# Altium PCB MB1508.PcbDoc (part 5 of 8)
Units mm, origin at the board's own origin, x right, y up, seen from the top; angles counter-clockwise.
Board outline 129 x 77 mm, 4 copper layers (Top Layer, GND, POWER, Bottom Layer), stack 1.582 mm thick; 399 components, 297 nets, 1407 pads, 1316 vias.
Unrouted connection lines stored in the file: 535.
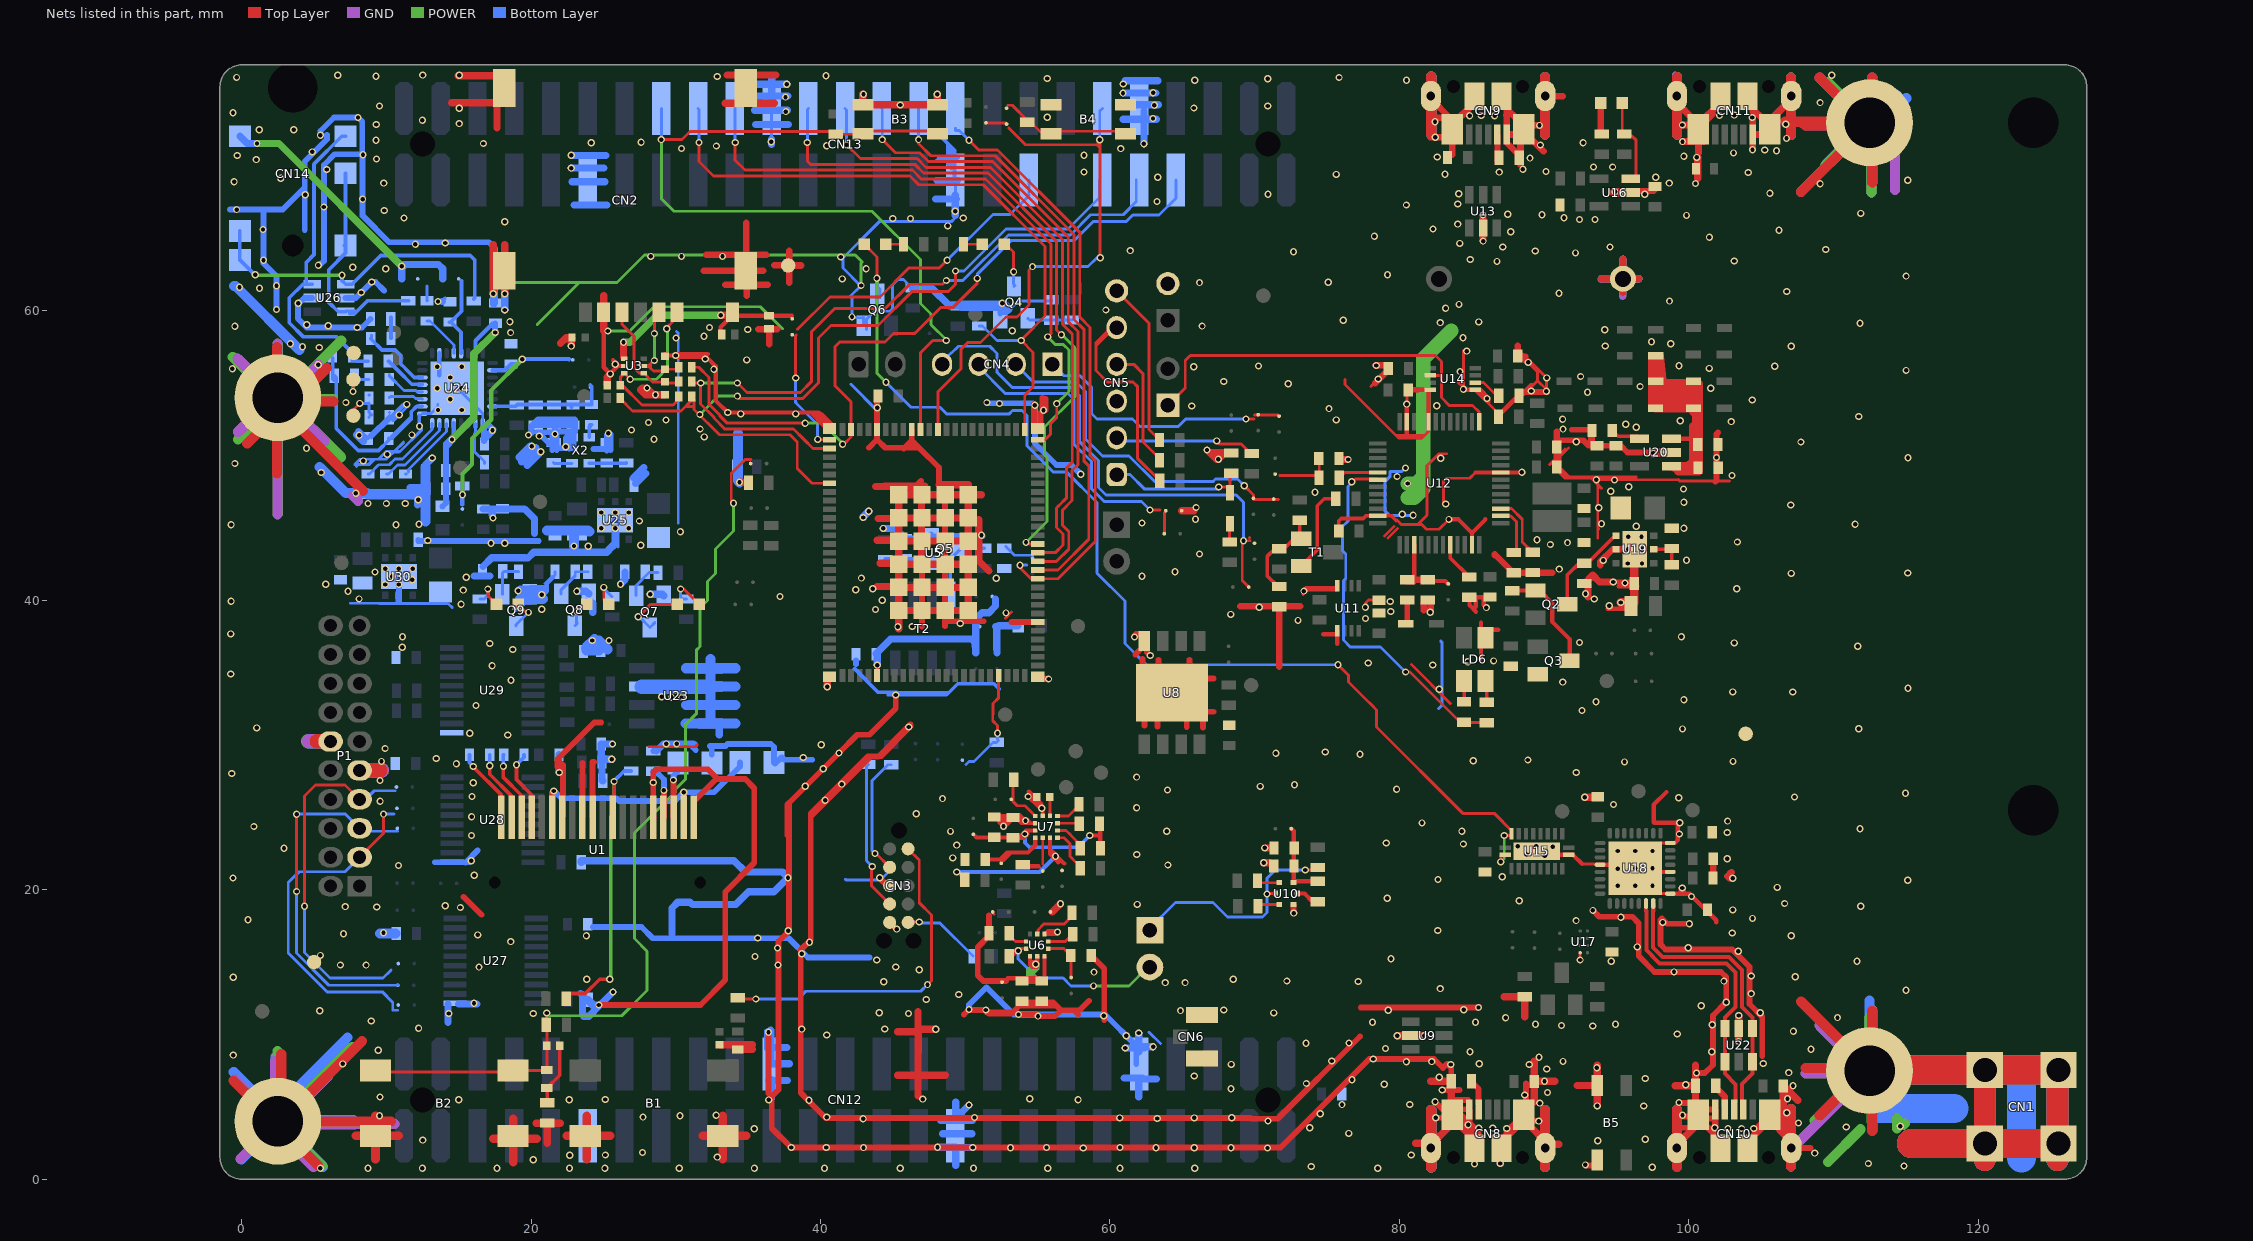
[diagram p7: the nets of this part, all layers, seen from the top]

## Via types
v1: diameter 0.5, hole 0.3, Top Layer to Bottom Layer, tented both sides, 1301 vias
v2: diameter 0.65, hole 0.4, Top Layer to Bottom Layer, tented both sides, 14 vias
v3: diameter 0.5/0.5/0.5/0.5 (per signal layer), hole 0.3, Top Layer to Bottom Layer, tented both sides, 1 vias

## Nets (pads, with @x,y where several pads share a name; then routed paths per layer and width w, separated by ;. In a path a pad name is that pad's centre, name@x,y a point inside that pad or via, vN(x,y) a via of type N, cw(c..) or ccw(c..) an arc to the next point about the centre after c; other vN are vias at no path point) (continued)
GND: (continued)
  Bottom Layer w1.5: CN1.4@120.46,1.3 CN1.4@120.46,2.46 CN1.3@120.46,7.54 ; CN1.1@125.483,1.317 125.483,2.46 CN1.2@125.483,6.397
  Bottom Layer w2: H3.1@113.255,4.873 118.335,4.873 ; 115.38,2.46 CN1.4@120.46,2.46 123.008,2.46 ; H3.1@115.38,7.54 CN1.3@120.46,7.54 CN1.2@125.54,7.54 ; 123.008,1.47 123.008,2.46 ; 123.008,6.55 123.008,2.46 ; CN1.1@125.54,2.46 125.483,2.46 123.008,2.46
  other v1: 5.442,0.762 8.734,0.762 12.488,0.762 17.643,0.762 22.66,0.762 25.1,0.762 30.246,0.762 35.433,0.762 40.276,0.762 45.516,0.762 50.569,0.762 55.705,0.762 60.699,0.762 65.865,0.762 78.5,0.762 97.483,0.829 73.906,0.871 114.869,0.909 92.856,0.987 85.199,1.051 112.412,1.088 20.145,1.337 32.857,1.524 22.68,1.651 25.136,1.673 80.816,1.673 108.704,1.8 27.701,1.838 58.159,2.155 70.885,2.155 42.973,2.181 53.13,2.178 63.188,2.178 65.83,2.178 68.37,2.178 93.709,2.658 12.509,2.7 96.996,2.751 76.496,3.163 35.415,3.477 102.711,3.502 103.651,3.502 104.489,3.502 85.49,3.527 86.455,3.527 73.805,3.556 101.796,3.552 110.888,3.607 114.622,3.665 84.753,3.756 107.586,3.884 70.922,4.021 42.945,4.174 63.265,4.189 68.421,4.244 50.646,4.264 27.73,4.288 40.435,4.289 9.527,4.389 30.295,4.389 32.788,4.416 99.572,4.416 74.533,4.528 106.775,4.594 96.893,5.061 76.041,5.153 80.713,5.164 89.706,5.254 99.33,5.3 39.211,5.449 15.003,5.483 22.635,5.483 36.417,5.478 57.802,5.483 25.122,5.504 47.06,5.534 54.463,5.556 106.826,5.556 9.56,5.674 88.665,5.813 90.236,5.991 68.37,6.242 107.207,6.448 99.79,6.524 78.962,6.56 73.577,6.613 76.732,6.877 96.996,6.956 82.757,7.037 65.829,7.134 106.902,7.362 90.18,7.613 93.651,7.693 83.559,7.921 88.969,7.921 68.379,7.932 6.991,7.965 85.519,7.98 105.149,7.997 80.486,8.115 82.238,8.124 91.306,8.138 75.336,8.168 89.655,8.429 -0.578,8.574 84.885,8.81 101.593,8.81 9.442,8.909 108.45,8.975 79.039,9.031 73.55,9.397 76.525,9.407 61.122,9.916 40.435,9.96 99.206,10.029 107.232,10.22 38.699,10.371 44.443,10.375 12.228,10.431 93.361,10.587 91.208,10.616 101.629,10.668 89.407,10.707 94.936,10.707 78.149,10.842 85.261,10.842 8.953,10.934 87.344,11.15 110.279,11.165 59.574,11.293 14.306,11.444 20.145,11.444 46.087,11.444 44.062,11.503 71.329,11.489 104.946,11.503 5.393,11.644 64.873,11.649 79.232,11.675 67.858,11.689 84.446,11.706 100.857,11.985 16.059,12.156 47.313,12.417 49.556,12.758 104.311,12.823 25.66,12.934 115.014,13.058 82.823,13.168 63.823,13.582 65.196,13.582 44.376,13.636 77.159,13.66 102.427,13.687 72.231,13.698 23.844,13.82 68.523,13.82 -0.578,13.947 107.359,13.992 104.311,14.043 58.905,14.31 46.825,14.474 16.405,14.656 45.202,14.659 6.822,14.804 8.602,14.793 37.059,14.804 94.649,15.059 111.623,15.059 43.884,15.148 79.419,15.226 35.473,15.389 5.442,15.463 38.699,15.578 103.423,15.744 37.026,15.972 99.968,15.992 96.447,16.049 39.236,16.379 18.592,16.417 35.665,16.663 23.824,16.815 107.08,16.822 16.313,16.88 7.034,16.961 102.998,17.014 9.803,17.032 37.765,17.167 82.655,17.182 45.271,17.279 98.2,17.744 92.216,17.866 0.438,17.921 104.405,18.022 95.311,18.105 103.039,18.606 15.115,18.775 9.335,18.81 7.161,18.834 111.877,18.854 14.077,18.887 61.89,18.987 106.622,19.046 88.284,19.233 79.169,19.413 100.186,19.531 106.114,20.164 95.097,20.279 96.297,20.279 115.141,20.658 82.67,20.711 -0.604,20.817 87.114,20.901 16.071,21.004 95.097,21.453 96.297,21.479 97.497,21.479 10.836,21.681 64.005,21.712 15.859,21.996 102.658,22.137 49.132,22.2 90.044,22.334 61.861,22.436 88.803,22.433 95.097,22.679 96.297,22.679 2.927,22.874 70.706,22.891 90.594,22.969 88.193,23.006 89.467,22.994 49.417,23.084 84.428,23.161 79.089,23.235 15.881,23.749 99.353,23.854 102.658,23.958 48.981,24.033 63.931,24.036 84.321,24.05 111.837,24.222 0.844,24.373 81.561,24.62 102.683,24.742 54.166,24.778 15.891,25.045 46.62,25.249 55.287,25.625 61.842,25.661 94.797,25.89 9.566,26.108 40.32,26.178 48.431,26.298 99.305,26.362 107.305,26.409 15.914,26.441 114.973,26.663 63.976,26.89 79.812,26.943 38.948,27.147 70.386,27.142 72.759,27.262 41.47,27.299 16.008,27.396 9.564,27.548 61.842,27.782 -0.68,28.034 92.222,28.1 40.193,28.363 14.838,28.712 95.564,28.836 9.662,28.869 103.058,28.869 85.108,28.913 88.883,28.963 13.455,29.073 38.801,29.135 77.286,29.37 71.469,29.435 74.88,29.515 9.911,29.758 40.056,30.027 29.344,30.079 30.055,30.079 18.384,30.698 15.763,30.821 99.572,31.115 111.75,31.129 1.047,31.186 46.104,31.246 92.618,32.381 16.195,32.733 93.589,32.983 99.663,33.135 29.7,33.294 30.399,33.287 29.027,33.333 103.032,33.671 107.178,33.665 82.757,33.853 115.146,33.919 91.298,34.349 18.614,34.476 -0.756,34.903 17.307,35.473 82.306,35.531 77.844,35.665 84.735,35.753 86.515,35.814 18.726,36.604 11.09,36.749 111.682,36.82 17.137,37.022 103.143,37.057 92.449,37.08 24.233,37.224 25.381,37.224 61.699,37.462 11.115,37.486 99.492,37.476 -0.756,37.682 45.349,38.167 46.34,38.192 49.656,38.398 72.993,38.614 77.664,38.741 68.345,39.029 52.817,39.132 79.406,39.232 43.799,39.367 20.731,39.376 86.017,39.497 70.323,39.518 94.507,39.62 15.165,39.723 -0.731,39.932 79.38,39.921 44.265,39.998 8.116,40.099 93.462,40.087 37.202,40.263 20.732,40.393 92.868,40.454 7.351,40.625 73.403,40.638 19.103,40.666 15.317,40.705 42.442,40.73 103.324,40.794 43.61,40.807 9.916,41.093 5.81,41.105 95.599,41.197 11.797,41.414 52.14,41.528 42.825,41.534 15.519,41.594 10.388,41.651 62.216,41.67 107.08,41.861 115.141,41.886 9.215,41.962 64.499,41.978 91.057,42.157 9.916,42.193 10.866,42.193 11.816,42.193 95.774,42.54 96.771,42.54 94.089,42.761 99.841,42.762 66.191,43.201 95.799,43.541 96.746,43.541 23.955,43.73 27.584,43.806 90.439,43.857 17.233,43.94 18.177,43.937 91.622,43.99 103.363,44.026 12.863,44.134 89.508,44.18 95.814,44.404 96.731,44.404 30.318,44.744 24.859,44.973 25.809,44.973 26.759,44.973 99.663,44.981 96.37,45.115 -0.731,45.229 10.663,45.225 12.254,45.251 111.496,45.251 93.967,45.285 62.22,45.346 27.485,45.482 65.912,45.61 17.365,45.684 80.203,45.942 24.859,46.073 25.809,46.073 26.759,46.073 93.779,46.394 65.957,46.419 107.051,46.588 8.73,46.688 10.001,46.688 11.313,46.688 99.663,46.783 12.206,46.948 74.174,47.472 94.608,47.545 99.635,47.689 95.858,47.85 94.873,48.311 79.844,48.551 102.988,48.629 5.496,48.838 -0.468,49.455 8.401,49.635 82.861,49.823 115.146,49.85 101.921,49.874 10.065,50.085 20.667,50.269 4.483,50.512 20.057,50.651 92.219,50.954 107.75,50.937 28.492,51.127 31.96,51.294 20.567,51.35 8.115,51.402 11.765,51.43 19.82,51.423 25.342,51.549 26.935,51.773 31.681,51.842 91.31,51.83 96.366,51.956 95.648,52.16 28.112,52.287 102.937,52.35 99.407,52.414 29.328,52.464 75.642,52.47 91.282,52.509 111.75,52.707 10.89,52.814 34.496,52.882 38.284,52.882 13.568,53.148 15.213,53.15 75.145,53.248 43.923,53.305 65.649,53.43 82.579,53.447 11.406,53.541 52.366,53.597 7.202,53.676 104.385,53.847 14.413,53.9 86.055,53.948 92.999,54.385 89.122,54.467 13.513,54.65 15.213,54.65 101.517,54.65 96.638,54.775 72.33,54.97 67.858,55.125 14.413,55.4 92.525,55.47 84.197,55.804 115.019,55.889 32.632,55.971 -0.639,56.007 101.415,56.028 13.513,56.15 15.213,56.15 65.789,56.147 105.937,56.181 70.267,56.194 99.33,56.207 34.898,56.614 84.654,57.223 5.358,57.475 4.21,57.527 107.08,57.556 94.227,57.578 3.369,57.73 98.75,57.731 97.428,57.87 30.016,58.13 84.397,58.151 31.945,58.248 18.584,58.502 53.249,58.625 94.202,58.69 34.965,58.712 32.327,58.852 -0.468,58.944 66.369,58.948 5.992,58.979 4.504,59.05 111.837,59.153 82.823,59.191 18.535,59.255 85.49,59.241 76.116,59.358 59.724,60.065 83.196,60.183 84.118,60.448 52.555,60.525 98.672,60.677 91.03,61.214 106.775,61.337 1.229,61.559 -0.146,61.642 66.191,61.957 75.094,61.982 41.502,62.212 115.019,62.406 79.18,62.498 9.965,62.912 43.153,62.912 7.672,63.015 86.75,63.42 103.143,63.446 84.901,63.547 41.401,63.722 28.275,63.765 30.396,63.765 33.229,63.765 92.17,64.008 72.688,64.086 89.398,64.135 61.402,64.167 109.467,64.248 87.141,64.411 94.558,64.411 12.007,64.614 84.169,64.665 14.077,64.69 101.426,65.097 78.277,65.151 87.699,65.478 106.241,65.579 1.479,65.623 82.33,65.659 48.792,65.873 84.042,65.999 18.177,66.163 92.446,66.316 93.516,66.316 44.999,66.389 46.218,66.38 11.216,66.417 49.872,66.417 91.381,66.443 99.841,66.599 89.858,66.646 87.496,66.671 111.877,66.737 9.85,66.942 80.486,67.319 84.042,67.384 63.258,67.56 4.4,68.031 70.922,68.054 96.957,68.063 84.104,68.095 105.606,68.123 94.91,68.239 100.462,68.805 109.076,68.791 9.826,68.83 98.647,68.83 -0.523,68.918 115.141,69.024 2.707,69.172 63.308,69.238 97.719,69.244 75.632,69.432 83.153,69.44 104.108,69.567 58.207,69.595 86.912,69.592 90.138,69.629 5.873,69.776 88.538,69.796 93.421,69.948 94.737,69.948 1.009,70.456 9.317,70.493 89.031,70.558 100.552,70.608 82.619,70.634 99.663,70.685 -0.312,70.735 22.777,70.758 58.21,70.758 8.385,70.798 103.092,70.92 4.885,70.99 106.064,71.066 105.251,71.116 30.399,71.218 60.747,71.215 32.805,71.39 40.435,71.406 89.746,71.459 16.705,71.569 24.154,71.613 92.701,71.613 27.603,71.647 36.595,71.687 9.284,71.791 106.749,71.922 82.489,72.005 1.212,72.513 3.596,72.513 89.681,72.818 9.296,72.88 106.699,72.894 15.044,72.944 82.467,73.068 12.49,73.171 62.982,73.298 104.387,73.369 55.67,73.387 84.855,73.486 86.582,73.486 85.667,73.504 102.127,73.504 103.143,73.529 -0.604,73.689 37.607,73.771 15.044,74.01 65.804,74.025 9.527,74.161 70.907,74.161 63.072,74.217 45.51,74.234 109.076,74.393 37.582,74.775 42.97,74.97 62.985,75.076 60.915,75.681 65.861,75.946 80.497,75.946 70.914,76.037 55.67,76.057 75.836,76.124 -0.35,76.135 32.857,76.194 9.286,76.219 40.376,76.244 6.644,76.28 12.512,76.295 15.03,76.28 109.874,76.28
INT_HUM: CN7.1 R44.1 U10.3 | length 16.4
  Top Layer w0.2: v1(70.85,19.711) 70.85,19.73 70.843,19.737 U10.3@71.446,19.737 ; v1@73.502,21.377 74.206,21.377 R44.1@74.358,21.53
  Bottom Layer w0.2: CN7.1@62.611,17.197 64.534,19.119 67.115,19.119 68.117,18.117 70.543,18.117 70.85,18.423 v1(70.85,19.711) 70.85,20.801 71.426,21.377 v1@73.502,21.377
  other v1: 73.506,21.367
INT_PRE: CN7.2 R20.2 U6.7 | length 12.7
  Top Layer w0.2: R20.2@53.046,15.414 53.289,15.414 v1(53.659,15.785) ; R20.2@53.214,15.589 53.551,15.927 U6.7@54.218,15.927
  POWER w0.2: v1(58.87,13.354) 61.309,13.354 CN7.2@62.611,14.657
  Bottom Layer w0.2: v1(53.659,15.785) 53.659,15.222 54.975,13.906 56.769,13.906 57.321,13.354 v1(58.87,13.354)
ISOLATION_CTRL: LD4.2 Q6.3 U15.1 U15.19 | length 78
  Top Layer w0.2: LD4.2@43.023,64.608 43.897,63.734 v1(43.897,62.261) v1@43.897,62.131 ; v1@75.765,35.548 76.493,34.819 76.493,34.354 77.732,33.115 78.054,32.793 78.418,32.429 78.418,31.25 84.388,25.281 86.557,25.281 U15.19@87.759,24.079 ; v1(87.015,21.924) 87.015,22.408 U15.1@87.306,22.408 ; v1(87.25,23.753) 87.651,23.753 U15.19@87.756,23.858
  POWER w0.2: v1(43.897,62.261) 43.897,55.692 v1(44.526,55.063) ; v1(87.015,21.924) 87.25,22.158 v1(87.25,23.753)
  Bottom Layer w0.2: v1(43.897,62.261) 43.897,61.704 44.129,61.472 Q6.3@44.129,60.918 ; v1(44.526,55.063) 45.348,54.242 46.248,53.341 48.261,53.341 48.727,52.875 50.347,52.875 50.358,52.887 51.657,52.887 ; 51.666,52.887 53.049,52.887 ; 53.049,52.896 53.265,53.112 53.923,53.112 54.269,52.766 54.269,50.68 55.509,49.441 56.093,48.856 57.012,48.856 59.104,46.764 59.104,41.876 61.035,39.944 61.035,37.021 62.51,35.547 v1(75.765,35.547)
LED_STLK: R50.1 R52.1 U12.30 | length 25.6
  Top Layer w0.2: v1@76.769,48.26 76.712,48.203 v1(76.712,48.194) 76.779,48.194 76.972,48.388 78.519,48.388 U12.30@78.519,48.338 ; v1(80.432,35.043) 80.737,35.043 84.197,31.583 R50.1@84.469,31.583 ; R50.1@84.469,31.548 R52.1@86.049,31.548
  Bottom Layer w0.2: v1(76.712,48.194) 76.712,48.127 76.442,47.857 76.442,45.466 76.075,45.099 76.075,43.425 76.299,43.201 76.299,41.505 76.142,41.349 76.142,37.25 76.609,36.783 78.692,36.783 v1(80.432,35.043)
MIC: C81.1 CN14.1 R114.1 U26.6 | length 22
  Bottom Layer w0.254: U26.6@4.885,61.843 U26.6@4.473,61.843 ; CN14.1@7.179,72.069 6.918,72.069 4.994,70.145 4.994,63.89 4.473,63.368 U26.6@4.473,61.843 ; R114.1@7.661,56.548 R114.1@7.661,56.93 7.661,57.095 6.551,58.205 4.269,58.205 3.295,59.178 3.295,60.906 4.233,61.843 U26.6@4.473,61.843 ; R114.1@7.781,56.668 7.918,56.53 C81.1@8.734,56.53
NC_DWU: CN13.32 U5.27 | length 43.5
  Top Layer w0.2: v1(34.105,71.636) 34.105,70.403 34.78,69.728 46.349,69.728 46.958,69.12 51.413,69.12 55.919,64.613 55.919,63.889 55.918,63.887 55.918,58.422 v1(55.701,58.205) ; U5.27@55.013,51.094 55.507,51.094 55.882,51.469 55.882,52.188 56.326,52.632 v1(56.326,53.593)
  POWER w0.2: v1(55.701,58.205) 56.219,57.687 56.781,57.687 57.165,57.303 57.165,54.431 v1(56.326,53.593)
  Bottom Layer w0.2: CN13.32@34.08,73.995 34.105,73.97 v1(34.105,71.636)
NC_HWU: CN13.34 R77.2 U5.29 | length 47.3
  Top Layer w0.2: v1(31.609,71.636) 31.609,70.322 32.603,69.328 46.184,69.328 46.792,68.72 51.247,68.72 55.519,64.447 55.519,64.055 55.518,64.053 55.518,59.64 53.88,58.002 v1(53.88,57.959) 53.88,57.947 54.692,57.135 54.692,54.75 54.113,54.171 54.113,53.173 U5.29@54.113,51.794
  Bottom Layer w0.2: CN13.34@31.54,73.995 31.609,73.926 v1(31.609,71.636) ; R77.2@50.972,58.962 51.197,58.962 52.2,57.959 v1(53.88,57.959)
NC_PWR_BUTTON: B3.2 B3.4 CN13.36 R14.2 U5.41 | length 59
  Top Layer w0.2: v1(29,71.839) 30.434,71.839 30.984,72.389 40.885,72.389 R14.2@41.066,72.208 42.883,72.208 B3.4@42.925,72.25 ; B3.4@42.906,72.423 42.95,72.428 B3.2@48.1,72.428 ; U5.41@46.913,51.794 46.913,57.109 47.763,57.959 v1(48.698,57.959)
  POWER w0.2: v1(29,71.839) 29,67.774 29.887,66.887 43.558,66.887 46.901,63.544 46.901,60.518 47.634,59.786 47.634,59.048 48.698,57.984 v1(48.698,57.959)
  Bottom Layer w0.2: v1@29,71.888 CN13.36@29,73.995
NC_RST: CN13.12 SB6.1 SB8.2 U5.39 | length 39.4
  Top Layer w0.2: U5.39@48.113,51.794 48.113,54.411 49.72,56.018 49.72,57.363 50.174,57.817 51.052,57.817 52.81,59.575 53.578,59.575 54.418,60.415 54.418,62.824 v1(54.654,63.061) ; SB6.1@51.434,72.996 52.772,72.996 SB8.2@52.856,72.912 ; 53.009,72.646 54.171,71.483 59.136,71.483 ; 59.127,71.455 59.319,71.263 ; 59.167,71.519 v1@59.167,71.791 ; v1(59.296,71.821) 59.296,71.707 v1@59.328,71.676 ; v1(59.328,63.675) 59.328,71.483 ; 59.136,71.483 59.328,71.483 ; 59.136,71.483 v1@59.328,71.676 ; 59.328,71.483 v1@59.328,71.676
  Bottom Layer w0.2: v1(54.654,63.061) 58.484,63.061 59.099,63.675 v1(59.328,63.675) ; v1@59.347,71.821 v1(59.296,71.821) 59.296,73.811 CN13.12@59.48,73.995
NC_RST_IND: CN13.20 R73.1 SB37.2 U5.11 | length 42.9
  Top Layer w0.2: v1(50.266,71.791) 50.937,71.12 52.241,71.12 57.919,65.441 57.919,63.061 57.918,63.059 57.918,61.94 57.919,61.939 57.919,61.173 57.918,61.171 57.918,59.579 58.634,58.863 58.634,50 58.986,49.647 58.986,44.071 56.409,41.494 U5.11@55.013,41.494 54.539,41.494 53.742,42.291 53.791,42.34 v1(53.791,42.431)
  Bottom Layer w0.2: CN13.20@49.32,72.625 49.32,72.455 49.602,72.455 v1(50.266,71.791) ; R73.1@52.805,43.724 53.412,43.117 54.654,43.117 ; v1(53.791,42.431) 54.255,42.431
NC_SIM_CLK: CN13.7 R5.1 U5.49 | length 50.7
  Top Layer w0.2: R5.1@31.109,56.105 31.585,56.105 32.302,55.388 32.302,53.549 33.037,52.814 33.037,52.755 33.55,52.242 v1(38.937,52.242) ; v1(41.528,50.784) 41.605,50.784 42.113,51.292 U5.49@42.113,51.794 42.113,53.716 41.015,54.814 41.015,57.532 41.333,57.851 44.458,57.851 45.053,58.445 46.519,58.445 48.32,60.246 49.171,60.246 50.832,61.907 v1(50.832,62.248)
  POWER w0.2: v1(38.937,52.242) 40.136,52.242 41.528,50.85 v1(41.528,50.784)
  Bottom Layer w0.2: v1(50.832,62.248) 50.832,62.534 53.151,64.853 57.516,64.853 58.83,66.167 61.119,66.167 61.583,66.631 63.402,66.631 64.56,67.789 CN13.7@64.56,69.045
NC_SIM_DETECT: CN13.15 SB5.2 U5.52 | length 29.8
  Top Layer w0.2: v1(38.284,55.369) 38.284,58.291 38.322,58.329 38.305,58.346 ; 38.42,58.73 40.65,60.96 44.102,60.96 46.096,62.954 48.206,62.954 v1(48.749,63.497) ; v1(39.803,51.119) 39.755,51.119 39.729,51.094 U5.52@40.613,51.094
  Bottom Layer w0.2: v1(38.284,55.369) 38.284,53.691 38.322,53.653 38.305,53.636 38.509,53.432 38.524,53.432 39.803,52.154 v1(39.803,51.119) ; v1(48.749,63.497) 51.919,66.667 53.104,66.667 54.4,67.963 CN13.15@54.4,69.045
NC_SIM_IO: CN13.11 R4.1 R7.1 U5.57 | length 57.5
  Top Layer w0.2: R4.1@26.157,53.976 26.157,53.945 27.012,53.09 30.367,53.09 31.109,53.832 R7.1@31.109,54.073 31.26,53.922 31.26,53.402 ; 30.703,53.402 31.26,53.402 ; v1@34.154,54.113 34.314,53.953 38.778,53.953 39.861,55.036 39.861,58.137 40.724,59.001 43.978,59.001 46.307,61.33 48.817,61.33 49.333,61.846 v1(49.333,62.76) ; U5.57@40.613,48.094 39.409,48.094 38.392,49.11 38.392,50.932 37.883,51.442 33.012,51.442 31.26,53.193 31.26,53.402
  POWER w0.2: v1(31.665,52.843) 32.935,54.113 v1(34.258,54.113)
  Bottom Layer w0.2: v1(49.333,62.76) 49.926,62.76 52.819,65.653 57.105,65.653 59.28,67.828 CN13.11@59.28,69.045
NC_SIM_RST: CN13.9 R6.1 U5.53 | length 51.7
  Top Layer w0.2: R6.1@31.109,55.118 31.214,55.013 v1(31.718,55.013) 31.718,53.568 32.637,52.649 32.637,52.59 33.385,51.842 38.136,51.842 38.841,51.136 39.484,50.494 U5.53@40.613,50.494 ; v1(34.258,55.013) 34.917,54.353 38.613,54.353 39.366,55.107 39.366,58.546 40.981,60.16 44.481,60.16 46.162,61.841 48.44,61.841 v1(48.698,62.1)
  POWER w0.2: v1(31.718,55.013) v1(34.258,55.013)
  Bottom Layer w0.2: v1(48.698,62.1) 49.832,62.1 52.985,65.253 57.271,65.253 58.664,66.646 60.915,66.646 61.82,67.551 CN13.9@61.82,69.045
NC_UART0_CTS: CN13.24 U5.13 | length 42.8
  Top Layer w0.2: v1(44.265,71.839) 45.176,70.928 46.846,70.928 47.455,70.32 51.91,70.32 57.119,65.11 57.119,63.392 57.118,63.39 57.118,59.248 57.797,58.568 57.797,49.372 57.389,48.963 57.389,46.889 56.711,46.212 56.711,45.201 57.153,44.759 57.153,43.53 56.317,42.694 U5.13@55.013,42.694
  Bottom Layer w0.2: CN13.24@44.24,73.995 44.265,73.97 v1(44.265,71.839)
NC_UART0_RTS: CN13.22 U5.12 | length 41.7
  Top Layer w0.2: v1(46.78,71.839) 46.78,71.56 47.62,70.72 52.075,70.72 57.519,65.276 57.519,63.226 57.518,63.225 57.518,61.775 57.519,61.773 57.519,61.338 57.518,61.337 57.518,59.413 58.197,58.734 58.197,49.641 58.539,49.3 58.539,44.226 56.406,42.094 U5.12@55.013,42.094
  Bottom Layer w0.2: v1(46.78,71.839) CN13.22@46.78,73.995
NC_UART0_RX: CN13.28 U5.15 | length 46.9
  Top Layer w0.2: v1(39.091,71.636) 39.091,70.348 39.311,70.128 46.515,70.128 47.123,69.52 51.578,69.52 56.319,64.778 56.319,63.723 56.318,63.722 56.318,58.679 v1(56.646,58.351) ; v1@54.261,44.053 54.42,43.894 U5.15@55.013,43.894 ; v1@56.609,58.313 v1@56.64,58.281
  POWER w0.2: v1(54.203,44.002) 55.644,45.443 55.644,49.908 55.489,50.063 55.489,51.978 57.585,54.074 57.585,57.448 56.752,58.281 v1@56.64,58.281
  Bottom Layer w0.2: v1(39.091,71.636) 39.091,73.926 CN13.28@39.16,73.995
NC_UART0_TX: CN13.26 U5.14 | length 44.1
  Top Layer w0.2: v1(41.802,71.483) 42.757,70.528 46.681,70.528 47.289,69.92 51.744,69.92 56.719,64.944 56.719,63.558 56.718,63.556 56.718,59.082 57.397,58.402 57.397,49.538 56.989,49.129 56.989,47.055 56.49,46.556 ; U5.14@55.013,43.294 56.228,43.294 56.753,43.819 56.753,44.593 56.311,45.035 56.311,46.378 56.464,46.531
  Bottom Layer w0.2: CN13.26@41.7,73.995 41.802,73.893 v1(41.802,71.483)
NetB2_1: B2.1 B2.2 C1.2 R1.1 SB2.2 U2.1 | length 64.1
  Top Layer w0.2: B2.1@9.25,7.5 9.335,7.415 18.665,7.415 B2.2@18.75,7.5 21.051,7.5 U2.1@21.097,7.546 21.097,10.447 R1.1@20.881,10.663 ; R1.1@20.96,10.749 R1.1@21.041,10.668 ; R1.1@21.081,11.116 v1(21.081,11.481) ; v1(33.994,46.71) 33.835,46.869 33.835,48.761 34.802,49.729 35.199,49.729
  POWER w0.2: v1(21.081,11.481) 21.267,11.294 26.272,11.294 28.016,13.038 28.016,15.744 27.138,16.622 27.138,23.932 30,26.794 30,26.963 30.672,27.635 30.672,31.423 31.445,32.196 31.445,36.585 31.665,36.805 31.665,39.456 32.192,39.983 32.192,41.304 32.749,41.862 32.749,43.555 33.994,44.799 v1(33.994,46.71)
NetB4_2: B4.2 B4.4 R16.1 SB8.1 | length 9.2
  Top Layer w0.2: 52.95,74.215 53.253,74.215 54.278,73.19 R16.1@54.278,73.043 54.503,73.043 55.297,72.25 B4.4@55.925,72.25 56.087,72.412 60.913,72.412 B4.2@61.075,72.25
NetC1_1: C1.1 R2.2 U2.2 | length 4.3
  Top Layer w0.254: R2.2@21.122,5.284 21.122,6.27 U2.2@21.097,6.296 21.988,7.187 C1.1@21.988,9.22
NetC3_2: C3.2 CN2.C7 R7.2 U3.3 | length 13.3
  Top Layer w0.2: v1(26.842,55.279) 26.842,55.3 U3.3@26.448,55.694 26.168,55.413 C3.2@26.168,54.862 26.301,54.862 27.672,53.49 29.821,53.49 30.209,53.879 R7.2@30.209,54.073 ; v1(29.381,58.772) 29.381,58.836 CN2.C7@29.85,59.305 ; CN2.C7@30.095,59.324 CN2.C7@30.095,59.895
  POWER w0.2: v1(26.842,55.279) 28.657,55.279 29.428,56.05 v1@29.428,58.657
NetC4_2: C4.2 CN2.C3 R5.2 U3.5 | length 7.2
  Top Layer w0.2: U3.5@27.798,56.194 27.848,56.244 28.152,56.244 28.254,56.346 ; U3.5@27.834,56.168 28.138,56.168 ; 28.17,56.127 28.254,56.043 ; CN2.C3@28.519,59.683 28.523,59.678 v1(28.523,58.434) ; v1@28.553,56.645 28.254,56.346 ; CN2.C3@28.62,59.69 CN2.C3@28.825,59.895 ; R5.2@30.209,56.105 30.075,55.971 C4.2@29.255,55.971 29.123,55.838 28.459,55.838 28.254,56.043 ; 28.254,56.043 28.254,56.346
  POWER w0.2: v1@28.523,56.574 v1(28.523,58.434)
  other v1: 28.523,56.57
NetC5_2: C5.2 CN2.C2 R6.2 U3.4 | length 7.6
  Top Layer w0.2: CN2.C2@26.285,59.895 26.285,59.078 27.115,58.248 27.115,56.078 27.499,55.694 U3.4@27.798,55.694 28.398,55.094 C5.2@29.255,55.094 ; C5.2@29.255,55.022 R6.2@30.114,55.022
NetC8_2: C8.2 SB11.1 U7.10 | length 5.1
  Top Layer w0.3: C8.2@51.387,22.094 52.424,22.094 52.899,22.569 54.344,22.569 54.846,23.072 U7.10@54.846,23.596 ; 52.641,22.062 53.116,22.537
NetC9_2: C9.2 C10.2 R26.2 R27.2 SB7.1 U7.9 | length 13.7
  Top Layer w0.254: SB7.1@50.565,23.829 50.786,23.608 C10.2@53.379,23.608 ; C10.2@53.379,23.631 53.721,23.631 53.995,23.905 54.046,23.854 v1(54.126,23.854) 54.126,24.035 54.187,24.096 U7.9@54.846,24.096 ; C10.2@53.618,23.554 54.055,23.554 v1@54.241,23.739 ; 54.075,23.574 v1@54.241,23.739 ; 54.329,24.082 54.329,23.828 v1@54.241,23.739 ; R27.2@59.329,22.985 R27.2@59.354,22.959
  Top Layer w0.3: v1(58.6,23.752) 59.312,23.752 59.329,23.736 ; R27.2@59.329,22.985 59.329,23.736 ; R26.2@59.329,24.382 59.329,23.736
  Bottom Layer w0.254: v1(54.126,23.854) 54.126,23.251 54.443,22.934 57.782,22.934 v1(58.6,23.752)
NetC11_1: C11.1 C13.2 R19.1 SB9.2 SB12.1 U6.10 | length 11.4
  Top Layer w0.2: 51.997,18.31 51.997,18.311
  Top Layer w0.3: 52.937,13.892 52.938,13.89 53.861,13.89 53.863,13.892 C13.2@55.086,13.892 ; 54.408,13.64 C13.2@55.292,13.64 ; C13.2@55.292,13.615 55.416,13.615 55.483,13.682 55.483,15.094 ; 55.48,15.107 U6.10@55.48,15.414
  Top Layer w0.4: R19.1@51.627,16.797 50.863,16.033 50.863,14.074 51.251,13.686 52.826,13.686 ; R19.1@51.645,16.981 51.645,18.217
NetC12_1: C12.1 U7.5 | length 1.5
  Top Layer w0.2: C12.1@55.837,26.553 55.859,26.531 U7.5@55.859,25.109
NetC14_2: C14.2 SB16.1 U6.1 | length 3.3
  Top Layer w0.2: U6.1@55.743,15.927 56.826,15.927 C14.2@57.302,15.451 57.302,13.944 SB16.1@57.291,13.933
NetC16_2: C16.2 C17.1 R45.1 SB27.2 U10.1 | length 6.4
  Top Layer w0.2: C17.1@72.74,22.891 72.74,23.963
  Top Layer w0.3: SB27.2@72.537,24.222 72.696,24.063 72.696,22.891 72.696,20.677 U10.1@72.791,20.582 ; U10.1@72.696,20.487 U10.1@72.791,20.582 ; R45.1@74.279,20.582 U10.1@72.791,20.582
NetC18_1: C18.1 R42.2 SB26.1 | length 4
  Top Layer w0.2: 71.739,48.616 74.468,48.616 C18.1@74.468,49.912
NetC34_2: C34.2 U20.4 | length 2
  Top Layer w0.254: C34.2@94.72,51.746 95.128,51.337 U20.4@96.527,51.337
NetC40_2: C40.2 C41.2 D7.2 D8.2 D9.2 D10.2 D11.2 U20.1 U20.3 | length 49
  Top Layer w0.2: 99.786,49.364 100.189,49.768
  Top Layer w0.3: U20.3@98.803,51.167 100.301,51.167
  Top Layer w0.6: D10.2@97.497,53.308 D9.2@97.497,56.808 ; D9.2@97.704,56.808 D10.2@97.704,53.277 ; 97.757,53.752 97.988,53.752 ; D10.2@97.759,53.331 D10.2@97.704,53.277 ; 97.833,54.014 97.988,54.014 ; 97.858,54.271 97.988,54.271 ; 97.858,54.667 97.988,54.667 ; D10.2@97.988,53.359 97.988,53.752 ; D9.2@97.988,56.808 97.988,54.667 ; D9.2@98.005,56.86 98.264,54.292 ; D7.2@98.035,55.005 100.323,55.005 D8.2@100.323,53.277 ; U20.1@98.803,49.267 100.509,49.267 C41.2@100.559,49.317 ; U20.1@98.998,49.226 99.287,48.938 99.553,48.938 99.58,48.911 100.675,48.911 C41.2@100.675,49.433 ; 100.045,53.752 97.988,53.752 ; 100.121,54.014 97.988,54.014 ; 100.147,54.271 97.988,54.271 ; 100.147,54.667 97.988,54.667 ; C41.2@100.323,49.451 100.323,52.015 100.524,52.216 100.524,52.837 100.323,53.038 D8.2@100.323,53.161 ; 100.667,52.894 D11.2@100.667,54.967 ; D8.2@100.675,53.113 C41.2@100.675,49.433 ; D10.2@97.704,53.277 D8.2@100.323,53.277 ; 97.988,53.752 97.988,54.014 ; 97.988,54.014 97.988,54.271 ; 97.988,54.271 97.988,54.667 ; D8.2@100.323,53.161 100.559,52.925 C41.2@100.559,49.317 ; D8.2@100.323,53.161 D8.2@100.323,53.277 ; C41.2@100.559,49.317 C41.2@100.675,49.433
NetC51_1: C51.1 SB38.1 SB41.1 SB42.1 U5.84 | length 13.8
  Top Layer w0.3: U5.84@43.913,34.794 43.917,34.798 v1(43.917,35.524)
  Bottom Layer w0.5: v1(43.917,35.524) 43.917,36.219 43.828,36.308 44.848,37.329 50.435,37.329 50.689,37.075 50.689,36.813 ; SB42.1@50.722,36.371 50.722,38.695 51.164,39.137 51.636,39.137 52.1,39.601 52.1,40.087
NetC52_1: C52.1 U1.6 U1.19 | length 18.1
  Top Layer w0.4: U1.6@21.45,24.999 21.45,26.71 v1(21.561,26.821) ; v1@30.516,26.735 30.528,26.735 30.55,26.757 U1.19@30.55,24.999
  Bottom Layer w0.4: v1(21.561,26.821) 21.597,26.821 22.099,26.319 25.892,26.319 26.081,26.13 29.944,26.13 v1(30.55,26.735) ; v1@30.516,26.735 v1(30.55,26.735) ; C52.1@34.43,28.784 34.43,28.517 32.647,26.735 v1(30.55,26.735)
NetC53_1: C53.1 X2.3 | length 0.9
  Bottom Layer w0.254: X2.3@24.03,51.263 24.03,51.975 C53.1@24.184,52.13 C53.1@24.182,52.13
NetC53_2: C53.2 C56.2 R84.1 R86.2 R89.1 SB47.2 U24.31 | length 9.7
  Bottom Layer w0.254: U24.31@17.338,53.4 18.914,53.4 R89.1@19.019,53.505 19.044,53.53 C56.2@22.884,53.53 ; C56.2@22.789,53.335 C56.2@22.789,53.505 ; 24.089,54.885 24.184,54.79 C53.2@24.184,53.53 C53.2@24.074,53.53 ; C56.2@22.884,53.53 C56.2@22.884,53.515 24.059,53.515 C53.2@24.074,53.53 ; C56.2@22.884,53.53 C53.2@24.074,53.53
NetC54_2: C54.2 R85.1 X2.4 | length 2.6
  Bottom Layer w0.254: X2.4@24.03,49.463 26.55,49.463 R85.1@26.579,49.492
NetC55_1: C55.1 U1.18 | length 3.3
  Top Layer w0.4: v1(29.834,27.585) 29.85,27.57 U1.18@29.85,24.999
  Bottom Layer w0.4: v1(29.834,27.585) 29.834,27.878 C55.1@30.093,28.136
NetC57_1: C57.1 R97.1 SB48.2 SB51.2 U24.26 | length 17.7
  POWER w0.3: v1(15.26,47.303) 15.26,48.744 15.92,49.404 15.92,51.185 17.081,52.346 17.102,52.346 17.238,52.482 17.238,54.497 v1(19.397,56.656)
  Bottom Layer w0.3: 15.256,46.627 R97.1@15.256,47.656 ; U24.26@17.338,55.9 18.177,55.9 C57.1@18.609,56.332 19.072,56.332 v1(19.397,56.656) 19.412,56.672 22.601,56.672 22.618,56.655
NetC60_1: C60.1 C65.1 C66.2 L2.1 U24.5 U24.23 | length 19.6
  POWER w0.5: v1(14.531,51.113) 16.044,52.626 16.044,57.031 v1(17.516,58.504)
  Bottom Layer w0.2: 14.244,50.58 14.706,51.042 14.706,51.35 ; 14.31,50.93 14.31,51.014 14.31,51.148 14.642,51.479
  Bottom Layer w0.3: v1@14.565,51.079 14.663,51.177 U24.5@14.663,52.225 ; U24.23@16.163,57.075 16.163,57.931 C60.1@17.338,59.106
  Bottom Layer w0.4: L2.1@13.884,46.491 14.113,46.72 C66.2@14.113,47.709 14.113,50.816 14.31,51.014 14.41,51.113 v1(14.531,51.113) ; v1(17.516,58.504) 17.516,59.139 C60.1@17.531,59.153
NetC62_1: C62.1 SB50.1 U24.21 | length 5.7
  Bottom Layer w0.254: C62.1@14.347,59.222 C62.1@14.467,59.222 ; U24.21@15.163,57.075 15.163,58.526 C62.1@14.467,59.222 ; 15.194,62.077 15.194,59.984 14.449,59.239 C62.1@14.467,59.222
NetC67_1: C67.1 U24.20 | length 3.1
  Bottom Layer w0.2: C67.1@12.797,59.296 13.011,59.296 14.663,57.644 U24.20@14.663,57.075
NetC71_2: C71.2 U24.6 | length 4.5
  Bottom Layer w0.2: C71.2@11.33,48.73 C71.2@11.382,48.73 ; C71.2@11.535,48.865 11.535,49.035 14.163,51.664 U24.6@14.163,52.225
NetC76_1: C76.1 R111.2 | length 2.6
  Bottom Layer w0.2: C76.1@10.362,58.319 R111.2@10.362,59.503
  Bottom Layer w0.254: R111.2@10.308,59.561 10.326,59.544 C76.1@10.326,58.105
NetC76_2: C76.2 U24.14 | length 5.3
  Bottom Layer w0.2: C76.2@8.962,58.041 C76.2@8.962,58.319
  Bottom Layer w0.254: C76.2@8.926,58.105 8.926,58.078 8.962,58.041 9.702,57.302 10.621,57.302 11,56.923 11,56.325 11.297,56.029 11.925,55.4 U24.14@12.488,55.4
NetC77_2: C77.2 U24.7 | length 5.4
  Bottom Layer w0.2: C77.2@10.016,48.73 10.141,48.73 10.769,49.357 11.291,49.357 13.663,51.729 U24.7@13.663,52.225
NetC78_1: C78.1 R112.2 TP8.1 | length 2.7
  Top Layer w0.2: TP8.1@7.725,52.86 7.725,53.177 v1(8.157,53.609)
  Bottom Layer w0.2: v1(8.157,53.609) 8.77,53.609 8.796,53.634 8.796,52.996 8.987,52.805 R112.2@8.86,52.805 ; R112.2@8.807,52.64 R112.2@8.807,52.657 ; C78.1@8.807,54.175 C78.1@8.832,54.2
NetC78_2: C78.2 U24.11 | length 2.4
  Bottom Layer w0.2: C78.2@10.196,54.009 10.277,54.091 11.871,54.091 12.011,53.95 12.438,53.95 U24.11@12.488,53.9
NetC79_1: C79.1 R115.1 TP7.1 | length 3.1
  Top Layer w0.2: TP7.1@7.522,55.057 TP7.1@7.725,55.26 ; v1(7.696,54.43) 7.696,55.23 TP7.1@7.725,55.259
  Bottom Layer w0.2: v1(7.696,54.43) R115.1@7.696,55.43 ; R115.1@7.796,55.26 C79.1@8.796,55.26
NetC79_2: C79.2 U24.12 | length 2.8
  Bottom Layer w0.2: C79.2@10.196,55.596 10.196,55.523 11.228,54.491 12.036,54.491 12.127,54.4 U24.12@12.488,54.4
NetC80_2: C80.2 R114.2 R115.2 U24.10 | length 15.4
  Bottom Layer w0.254: R114.2@6.297,56.751 6.301,56.748 6.301,55.284 R115.2@6.365,55.219 ; R115.2@6.396,55.53 6.534,55.392 6.534,51.882 8.065,50.351 9.452,50.351 10.166,51.065 C80.2@10.166,51.191 10.379,51.191 11.724,52.535 11.724,52.689 ; C80.2@10.379,51.344 11.724,52.689 ; U24.10@12.488,53.4 12.089,53.4 11.724,53.035 11.724,52.689
NetC81_2: C81.2 U24.13 | length 3.4
  Bottom Layer w0.254: C81.2@10.134,56.53 10.153,56.53 10.843,55.84 11.76,54.923 12.465,54.923 U24.13@12.488,54.9 12.231,54.9 12.254,54.877 U24.13@12.338,54.877
NetC82_2: C82.2 U24.8 | length 6.1
  Bottom Layer w0.2: C82.2@8.746,48.73 8.827,48.73 9.444,49.346 10.196,49.37 10.603,49.757 11.125,49.757 13.163,51.795 U24.8@13.163,52.225
NetC83_1: C83.1 U1.3 | length 4.9
  Top Layer w0.254: v1(18.087,28.541) 18.087,27.753 19.35,26.491 U1.3@19.35,24.999
  Bottom Layer w0.254: v1(18.087,28.541) 18.087,29.306 C83.1@18.11,29.328
NetC83_2: C83.2 U1.4 | length 5
  Top Layer w0.254: v1(18.987,28.631) 18.987,27.615 20.05,26.553 U1.4@20.05,24.999
  Bottom Layer w0.254: v1(18.987,28.631) 18.99,28.631 19.51,29.15 C83.2@19.51,29.328
NetC85_1: C85.1 U1.2 | length 5
  Top Layer w0.254: v1(17.148,28.566) 17.148,27.988 18.65,26.486 U1.2@18.65,24.999
  Bottom Layer w0.254: C85.1@17.14,29.328 17.148,29.32 v1(17.148,28.566)
NetC85_2: C85.2 U1.1 | length 5.2
  Top Layer w0.254: v1(16.009,28.515) 16.009,28.485 17.95,26.544 U1.1@17.95,24.999
  Bottom Layer w0.254: C85.2@15.74,29.328 15.74,28.784 v1(16.009,28.515)
NetCN2_1: CN2.1 R8.1 R9.1 SB5.1 U3.1 | length 15.3
  Top Layer w0.3: U3.1@26.385,56.803 26.385,56.757 U3.1@26.448,56.694 ; R8.1@33.095,58.502 33.095,58.864 CN2.1@33.905,59.674 ; CN2.1@33.856,59.674 CN2.1@33.905,59.674 ; CN2.1@33.905,59.895 CN2.1@33.905,59.674 ; R9.1@36.443,59.666 38.031,59.666 ; R9.1@36.443,59.674 CN2.1@33.905,59.674
  Top Layer w0.5: U3.1@26.385,56.803 v1(26.385,57.841) ; v1(33.111,59.707) CN2.1@33.823,59.707
  POWER w0.5: v1(26.385,57.841) 26.834,57.841 28.7,59.707 v1(33.111,59.707)
NetCN3_2: CN3.2 R81.2 | length 8.3
  Top Layer w0.2: v1(43.765,22.502) 43.833,22.502 CN3.2@44.781,21.554
  Bottom Layer w0.2: v1(43.765,22.502) 43.573,22.694 43.573,27.548 44.659,28.634 R81.2@44.884,28.634
NetCN3_4: CN3.4 R83.2 | length 10.5
  Top Layer w0.2: v1(43.58,21.602) 43.573,21.602 43.538,21.567 v1@43.538,21.539 ; v1@43.63,21.632 v1@43.538,21.539 ; CN3.4@44.781,19.014 43.538,20.257 v1@43.538,21.539
  Bottom Layer w0.2: R83.2@43.309,28.659 43.173,28.523 43.173,22.009 v1(43.58,21.602)
NetCN3_6: CN3.6 R75.1 | length 5.9
  Top Layer w0.2: v1(46.825,17.769) 46.076,17.769 CN3.6@46.051,17.744 ; CN3.6@46.051,17.744 46.202,17.592 CN3.6@46.051,17.744
  Bottom Layer w0.2: v1(46.825,17.769) 46.893,17.702 48.245,17.702 R75.1@50.533,15.414
NetCN3_10: CN3.10 R12.1 | length 23.8
  Top Layer w0.2: R12.1@34.165,12.451 v1(35.534,12.451) ; CN3.10@46.051,22.824 46.826,22.048 46.826,19.104 47.681,18.249 47.681,13.686 ; v1(47.39,13.444) 47.633,13.686
  Bottom Layer w0.2: v1(35.534,12.451) 38.455,12.451 38.987,12.983 46.93,12.983 v1(47.39,13.444)
NetCN4_1: CN4.1 SB20.2 SB25.1 | length 18.7
  Top Layer w0.2: v1(69.409,52.53) 69.961,52.53 ; 69.987,52.814 71.605,52.814 SB25.1@71.689,52.73
  Bottom Layer w0.2: CN4.1@56.024,56.308 56.817,55.516 57.924,55.516 58.719,54.721 58.719,52.913 59.102,52.53 61.57,52.53 62.088,52.012 64.726,52.012 65.241,52.527 65.301,52.527 65.304,52.53 v1(69.409,52.53)
NetCN4_2: CN4.2 SB19.2 SB23.1 | length 24.3
  Top Layer w0.2: v1@69.41,47.918 v1(69.282,47.918) 69.916,47.284 SB19.2@69.916,47.047 ; SB19.2@69.916,46.971 71.638,46.971
  Bottom Layer w0.2: CN4.2@53.484,56.308 54.698,55.094 57.663,55.094 58.319,54.438 58.319,51.146 59.484,49.981 61.326,49.981 63.108,48.199 67.123,48.199 67.3,48.376 68.824,48.376 v1(69.282,47.918)
NetCN4_3: CN4.3 SB22.2 SB24.1 | length 21
  Top Layer w0.2: v1(62.773,46.239) 63.45,46.239 ; 63.784,44.738 63.784,46.055
  Bottom Layer w0.2: CN4.3@50.944,56.308 50.944,56.115 52.764,54.294 57.102,54.294 57.519,53.877 57.519,50.79 58.723,49.586 58.723,47.71 59.611,46.822 62.19,46.822 v1(62.773,46.239)
NetCN4_4: CN4.4 SB17.2 SB21.1 | length 36.2
  Top Layer w0.2: SB17.2@69.598,40.916 69.141,41.373 69.141,44.026 v1(69.23,44.115) 69.686,44.115 ; 69.649,44.302 69.649,44.329
  Bottom Layer w0.2: CN4.4@48.404,56.308 48.404,56.466 49.021,57.082 49.053,57.082 49.531,57.56 51.698,57.56 52.203,57.055 52.203,55.758 53.267,54.694 57.338,54.694 57.919,54.113 57.919,50.956 59.204,49.671 59.204,47.795 59.724,47.276 68.726,47.276 69.23,46.772 v1(69.23,44.115)
NetCN5_1: CN5.1 D1.1 R30.1 | length 9.9
  Top Layer w0.2: v1(67.528,47.826) 68.218,47.826 68.267,47.875 D1.1@68.308,47.833 ; D1.1@68.308,47.425 D1.1@68.308,47.833 ; R30.1@68.393,48.779 68.308,48.695 D1.1@68.308,47.833
  Bottom Layer w0.2: CN5.1@60.464,48.688 61.387,48.688 62.371,47.705 v1@67.488,47.705 ; v1(67.528,47.826) 67.584,47.826 67.597,47.813 v1@67.488,47.705 ; v1@67.541,47.742 67.504,47.705 v1@67.488,47.705
NetCN5_2: CN5.2 R34.1 | length 10
  Top Layer w0.2: v1(67.376,51.017) 67.376,50.982 67.371,50.977 67.549,50.799 69.065,50.799 69.069,50.803 69.73,50.143 R34.1@69.936,50.143
  Bottom Layer w0.2: CN5.2@60.464,51.228 60.715,50.977 60.755,51.017 v1(67.376,51.017)
NetCN5_4: CN5.4 R32.1 | length 8.5
  Top Layer w0.2: CN5.4@60.464,56.308 61.645,56.308 62.293,55.661 62.293,50.945 63.426,49.811 R32.1@63.426,49.691
NetCN5_5: CN5.5 R31.1 | length 16.3
  Top Layer w0.2: 59.065,57.627 CN5.5@60.1,58.662 ; CN5.5@60.464,58.241 CN5.5@60.464,58.848 60.071,58.848 59.037,57.814 59.037,55.873 59.819,55.09 61.594,55.09 61.893,54.792 61.893,49.822 R31.1@63.443,48.271
NetCN5_6: CN5.6 R33.1 | length 11.6
  Top Layer w0.2: CN5.6@60.464,61.388 62.704,59.148 62.704,51.797 R33.1@63.422,51.079 R33.1@63.422,51.156
NetCN8_4: CN8.4 R46.1 | length 2
  Top Layer w0.305: R46.1@84.999,6.484 R46.1@84.999,6.709
  Top Layer w0.4: R46.1@84.999,6.709 85.48,6.228 CN8.4@85.48,5.16
NetCN9_4: CN9.4 R48.1 | length 1.9
  Top Layer w0.4: R48.1@86.78,70.321 CN9.4@86.78,72.19
NetCN10_2: CN10.2 U18.15 U22.1 U22.6 | length 20.5
  Top Layer w0.279: U18.15@97.547,19.054 97.547,18.539 97.525,18.518 97.525,16.011 98.175,15.362 102.784,15.362 103.684,14.462 103.684,11.886 104.405,11.165 U22.1@104.405,10.415 ; CN10.2@103.78,4.81 103.78,5.09 103.684,5.187 103.684,6.583 104.391,7.29 U22.6@104.391,7.729 ; U22.6@104.391,8.115 U22.6@104.391,7.729 ; U22.1@104.391,10.415 U22.6@104.391,7.729
NetCN10_3: CN10.3 U18.14 U22.3 U22.4 | length 20.9
  Top Layer w0.254: U18.14@97.042,19.049 U18.14@97.047,19.054
  Top Layer w0.279: U18.14@97.047,19.054 97.047,18.539 97.068,18.518 97.068,15.822 97.985,14.905 ; 97.457,15.434 97.985,14.905 ; U22.3@102.491,10.415 102.491,7.288 103.226,6.552 103.226,5.314 103.13,5.217 CN10.3@103.13,4.81 ; U22.3@102.505,10.415 102.505,11.165 103.226,11.886 103.226,14.273 102.594,14.905 97.985,14.905
NetCN10_4: CN10.4 R67.2 | length 1.8
  Top Layer w0.45: R67.2@101.892,6.702 101.892,6.294 102.48,5.706 CN10.4@102.48,5.16
NetCN14_2: CN14.2 SB50.2 SB52.2 | length 19.9
  POWER w0.5: v1(1.061,71.569) 2.577,71.569 v1(11.063,63.083)
  Bottom Layer w0.2: 11.135,62.808 11.4,63.073
  Bottom Layer w0.5: CN14.2@-0.121,72.069 0.379,71.569 v1(1.061,71.569) ; SB52.2@11.063,62.212 v1(11.063,63.083) 11.185,63.205 13.608,63.205 13.894,62.919 SB50.2@13.894,62.212
NetCN14_3: CN14.3 CN14.5 R110.2 U26.3 | length 16.1
  Bottom Layer w0.2: U26.3@7.179,60.003 7.98,60.003
  Bottom Layer w0.254: CN14.5@7.11,64.519 CN14.5@7.179,64.519 ; CN14.3@7.179,69.519 CN14.5@7.179,64.519 ; U26.3@7.185,59.943 6.666,59.943 6.029,60.58 6.029,62.848 7.179,63.998 CN14.5@7.179,64.519 ; U26.3@7.49,59.825 7.808,59.825 8.693,60.71 R110.2@11.527,60.71
NetCN14_4: CN14.4 CN14.6 R102.2 U26.1 | length 22.8
  POWER w0.254: v1(0.934,62.493) 0.96,62.467 v1(6.929,62.467)
  Bottom Layer w0.254: CN14.4@-0.121,65.519 CN14.6@-0.121,63.519 v1@0.92,62.478 ; v1(6.929,62.467) 6.929,62.1 U26.1@7.185,61.843 7.62,61.843 9.608,63.831 15.801,63.831 16.107,63.525 16.107,60.893 R102.2@16.032,60.819
NetD1_2: D1.2 R29.1 | length 1.1
  Top Layer w0.2: R29.1@68.272,44.18 68.272,45.249 D1.2@68.308,45.285
NetD2_2: D2.2 R47.1 | length 1.7
  Top Layer w0.4: D2.2@80.432,38.382 80.548,38.498 R47.1@80.548,40.03
NetJP3_1: JP3.1 U12.13 U14.2 | length 28.6
  Top Layer w0.2: JP3.1@64.004,53.478 65.206,54.68 65.206,56.569 65.558,56.921 82.489,56.921 82.904,56.506 82.904,55.546 ; U14.2@82.151,55.546 82.904,55.546 ; U12.13@85.519,52.338 85.519,53.012 85.064,53.467 83.451,53.467 82.904,54.014 82.904,55.546
NetL1_2: L1.2 SB38.2 SB39.1 | length 3.3
  Bottom Layer w0.5: SB38.2@52.1,38.187 SB38.2@52.173,38.114 ; 52.173,36.604 SB38.2@52.173,38.114 ; SB39.1@52.194,36.377 SB39.1@52.194,36.477 ; L1.2@53.657,38.251 52.31,38.251 SB38.2@52.173,38.114
NetLD1_1: LD1.1 R118.1 | length 2.4
  Top Layer w0.2: v1(17.017,40.781) 17.017,40.317 LD1.1@17.609,39.725
  Bottom Layer w0.2: R118.1@16.466,40.096 16.762,40.096 17.017,40.351 v1(17.017,40.781)
NetLD1_2: LD1.2 Q9.3 | length 2.2
  Top Layer w0.2: LD1.2@19.109,39.725 19.668,39.166 v1(19.82,39.166)
  Bottom Layer w0.2: Q9.3@18.967,38.223 18.967,38.313 v1(19.82,39.166)
NetLD2_1: LD2.1 R98.1 | length 2.2
  Top Layer w0.2: v1(25.021,40.892) 25.021,40.063 LD2.1@25.359,39.725
  Bottom Layer w0.2: v1(25.021,40.892) 25.021,40.826 R98.1@25.596,40.251
NetLD2_2: LD2.2 Q8.3 | length 2
  Top Layer w0.2: v1(23.145,39.24) 23.145,39.278 23.592,39.725 LD2.2@23.859,39.725
  Bottom Layer w0.2: Q8.3@23.031,38.248 23.192,38.409 23.141,38.46 23.145,38.464 v1(23.145,39.24)
NetLD3_1: LD3.1 R88.1 | length 2.7
  Top Layer w0.2: v1(30.334,40.781) 30.553,40.781 LD3.1@31.609,39.725
  Bottom Layer w0.2: v1(30.334,40.781) 30.334,40.25 30.485,40.099 R88.1@30.727,40.099
NetLD3_2: LD3.2 Q7.3 | length 4.8
  Top Layer w0.2: v1(27.412,38.862) 28.275,39.725 LD3.2@30.109,39.725 ; LD3.2@30.215,39.619 LD3.2@30.321,39.725
  Bottom Layer w0.2: v1(27.412,38.862) 27.471,38.862 Q7.3@28.212,38.121 28.545,38.454 Q7.3@28.523,38.476
NetLD4_1: LD4.1 R15.1 | length 1.2
  Top Layer w0.2: LD4.1@44.523,64.608 R15.1@45.729,64.608
NetLD5_1: LD5.1 R17.1 | length 1.3
  Top Layer w0.2: R17.1@49.883,64.608 LD5.1@51.19,64.608
NetLD5_2: LD5.2 Q4.3 | length 3.3
  Top Layer w0.2: LD5.2@52.69,64.608 52.815,64.608 53.344,64.08 v1(53.344,62.713)
  Bottom Layer w0.2: v1(53.344,62.713) 53.344,61.862 53.445,61.76 Q4.3@53.372,61.687
NetLD6_2: LD6.2 R52.2 | length 1.7
  Top Layer w0.254: R52.2@86.049,32.948 86.049,34.02 85.958,34.111 LD6.2@85.958,34.42 LD6.2@86.067,34.311
NetLD6_3: LD6.3 R50.2 | length 1.5
  Top Layer w0.254: LD6.3@84.458,34.42 84.474,34.403 R50.2@84.474,32.948
  Top Layer w0.5: R50.2@84.458,32.964 R50.2@84.474,32.948
NetLD7_1: LD7.1 R64.1 | length 2.2
  Top Layer w0.45: LD7.1@93.904,74.368 93.904,72.303 R64.1@93.984,72.223
NetLD7_2: LD7.2 R57.1 U16.3 | length 6.2
  Top Layer w0.2: LD7.2@95.404,74.368 95.404,72.362 R57.1@95.544,72.223 95.934,72.223 96.366,71.791 96.366,69.211 96.281,69.126 U16.3@95.987,69.126
NetP1_2: P1.2 SB56.2 SB60.2 | length 24.4
  Top Layer w0.2: P1.2@8.15,22.246 9.803,23.899 v1(9.803,25.225)
  Bottom Layer w0.2: P1.2@8.15,22.246 7.15,21.246 3.975,21.246 3.22,20.49 3.22,15.629 5.904,12.945 9.716,12.945 10.442,12.219 10.442,11.675 10.775,11.675 ; v1(9.803,25.225) 10.515,25.225
NetP1_3: P1.3 SB55.2 SB58.2 | length 25
  Top Layer w0.2: v1(3.796,19.881) v1(3.796,25.222)
  Bottom Layer w0.2: v1(3.796,19.881) 3.796,15.619 6.013,13.402 SB55.2@10.798,13.402 ; v1@3.921,25.246 7.15,25.246 P1.3@8.15,24.246 P1.3@8.66,24.756 ; P1.3@8.67,24.045 10.757,24.045
NetP1_4: P1.4 SB54.2 SB61.2 | length 25
  Top Layer w0.2: v1(4.346,18.863) 4.346,26.483 5.108,27.246 7.15,27.246 P1.4@8.15,26.246
  Bottom Layer w0.2: v1(4.346,18.863) 4.346,15.663 6.107,13.902 9.77,13.902 10.311,14.443 ; P1.4@8.15,26.246 8.564,26.246 9.157,26.839 10.589,26.839
NetQ2_1: Q2.1 Q3.3 R59.1 | length 7.6
  Top Layer w0.3: R59.1@87.806,40.666 87.819,40.68 89.697,40.68 90.556,39.82 90.556,39.084 ; 90.557,39.083 90.557,38.527 91.784,37.3 Q3.3@91.784,35.833
NetQ2_3: Q2.3 R66.2 U19.1 | length 6.5
  Top Layer w0.254: Q2.3@91.606,39.73 91.606,41.744 92.548,42.686 R66.2@92.794,42.686 ; R66.2@92.794,42.563 R66.2@93.057,42.563 ; R66.2@93.102,42.718 93.158,42.718 94.919,44.479 U19.1@94.973,44.479
NetQ4_1: Q4.1 R70.1 R71.2 | length 3.1
  Bottom Layer w0.2: Q4.1@54.322,59.487 54.434,59.375 R70.1@57.37,59.375
NetQ5_1: Q5.1 R80.2 R82.1 | length 3.1
  Bottom Layer w0.254: R82.1@44.477,42.852 47.239,42.852 Q5.1@47.489,42.602
NetQ5_3: Q5.3 R76.1 T2.4 | length 5.1
  Bottom Layer w0.254: T2.4@48.974,40.415 48.974,42.838 49.728,43.592 R76.1@51.325,43.592
NetQ7_1: Q7.1 R90.1 R94.2 | length 2.6
  Bottom Layer w0.2: Q7.1@27.262,40.321 27.262,41.026 28.15,41.914 R90.1@28.771,41.914
NetQ8_1: Q8.1 R101.1 R107.2 | length 2.8
  Bottom Layer w0.2: Q8.1@22.081,40.448 22.081,40.735 23.05,41.704 R107.2@23.05,41.978 R101.1@23.92,41.978
NetQ9_1: Q9.1 R113.1 R116.2 | length 2.6
  Bottom Layer w0.2: Q9.1@18.017,40.423 18.017,41.889 18.117,41.99 19.119,41.99 R113.1@19.13,41.978
NetR3_2: R3.2 R96.1 U1.12 | length 20.4
  Top Layer w0.254: R3.2@22.425,12.476 22.779,12.83 23.749,12.83 24.739,13.82 v1(25.438,13.82) ; U1.12@25.625,26.031 25.737,26.143 v1(25.737,27.479)
  POWER w0.254: v1(25.438,13.82) 25.511,13.893 25.511,25.064 25.737,25.29 v1(25.737,27.479) v1@25.737,27.512
  Bottom Layer w0.254: v1(25.737,27.479) 25.737,27.512 26.43,28.205 R96.1@26.918,28.205
NetR18_2: R18.2 SB15.2 U7.12 | length 11.2
  Top Layer w0.2: v1(49.409,21.223) 49.45,21.223 R18.2@49.972,20.701
  Top Layer w0.3: U7.12@55.859,23.584 55.859,22.486 56.437,21.907 ; 55.955,22.697 56.835,21.816
  Bottom Layer w0.3: v1(49.409,21.223) 55.145,21.223 v1(56.238,22.316)
NetR19_2: R19.2 U6.6 | length 1.3
  Top Layer w0.2: R19.2@53.238,16.904 53.238,16.663 53.475,16.427 U6.6@54.218,16.427
NetR21_2: R21.2 SB10.2 U7.7 | length 3.5
  Top Layer w0.2: R21.2@53.347,27.59 53.289,27.533 53.289,26.113 53.595,25.807 54.136,25.807 U7.7@54.846,25.096
NetR22_2: R22.2 SB14.2 U7.11 | length 4.2
  Top Layer w0.2: R22.2@53.811,21.949 54.204,21.555 55.132,21.555 ; R22.2@54.174,21.681 55.102,21.681 ; 55.359,21.783 U7.11@55.359,23.584
NetR23_2: R23.2 U6.4 | length 3.2
  Top Layer w0.2: U6.4@54.98,16.939 55.03,16.939 55.03,17.226 55.449,17.644 56.865,17.644 57.327,18.107 R23.2@57.327,18.332
NetR24_2: R24.2 U6.2 | length 1.9
  Top Layer w0.2: U6.2@55.743,16.427 56.916,16.427 R24.2@57.429,16.939
NetR25_2: R25.2 U7.4 | length 1.8
  Top Layer w0.2: U7.4@56.371,25.096 57.131,25.096 57.869,25.834 R25.2@57.826,25.834
NetR26_1: R26.1 U7.3 | length 1.6
  Top Layer w0.2: U7.3@56.371,24.596 57.714,24.596 R26.1@57.929,24.382
NetR27_1: R27.1 U7.2 | length 2.1
  Top Layer w0.2: U7.2@56.371,24.096 56.972,24.096 57.309,23.759 57.309,23.757 57.484,23.582 57.486,23.582 57.954,23.114 R27.1@57.954,22.959
NetR28_2: R28.2 U7.1 | length 2.7
  Top Layer w0.2: U7.1@56.371,23.596 56.82,23.596 57.24,23.177 57.24,22.312 R28.2@57.696,21.856 ; R28.2@57.929,21.659 R28.2@57.929,21.716 ; R28.2@57.966,21.593 R28.2@57.966,21.646
NetR35_2: R35.2 U10.2 | length 1.5
  Top Layer w0.2: R35.2@70.28,20.624 70.417,20.487 U10.2@71.696,20.487
NetR36_2: R36.2 R37.1 R39.1 T1.1 | length 6.6
  Top Layer w0.254: R36.2@71.689,40.953 71.611,40.953 70.862,41.702 70.862,43.021 71.398,43.558 R37.1@71.689,43.558 72.033,43.558 72.746,44.271 T1.1@73.23,44.271 73.111,44.39 R39.1@73.111,45.528
NetR38_2: R38.2 U10.4 | length 1.5
  Top Layer w0.2: R38.2@70.24,18.848 70.379,18.987 U10.4@71.696,18.987
NetR42_1: R42.1 U12.29 | length 2.9
  Top Layer w0.2: R42.1@75.829,48.438 76.229,48.838 U12.29@78.519,48.838
NetR43_2: R43.2 T1.2 | length 6.3
  Top Layer w0.254: T1.2@73.23,42.371 74.33,43.471 74.33,46.539 74.807,47.015 R43.2@75.51,47.015 ; R43.2@75.611,47.015 R43.2@75.51,47.015 ; R43.2@75.637,46.888 R43.2@75.51,47.015
NetR45_2: R45.2 U10.6 | length 1.6
  Top Layer w0.3: U10.6@72.946,19.737 73.455,19.737 73.984,19.207 73.984,19.182 R45.2@74.279,19.182
NetR47_2: R47.2 R49.1 SB29.2 U12.39 | length 7.1
  Top Layer w0.2: R47.2@80.923,41.548 R49.1@81.851,41.548
  Top Layer w0.3: R47.2@81.019,41.256 80.534,41.256 80.458,41.332 R47.2@81.019,41.332 ; U12.39@81.019,43.838 R47.2@81.019,41.332 ; R49.1@81.643,41.259 R49.1@81.571,41.332 ; SB29.2@83.371,41.138 83.177,41.332 R49.1@81.571,41.332 ; R47.2@81.019,41.332 R49.1@81.571,41.332
NetR51_2: R51.2 U12.44 | length 2.8
  Top Layer w0.254: U12.44@83.519,43.838 83.519,42.93 R51.2@84.845,41.604
NetR56_2: R56.2 U14.6 | length 2
  Top Layer w0.2: U14.6@85.251,55.046 85.816,55.046 R56.2@86.785,54.077 ; R56.2@86.785,54.229 R56.2@86.861,54.153
NetR60_2: R60.2 U12.2 | length 3.6
  Top Layer w0.2: U12.2@87.019,45.838 87.693,45.838 88.097,45.434 88.097,43.409 R60.2@87.843,43.155
NetR61_2: R61.2 U12.3 | length 4.5
  Top Layer w0.2: U12.3@87.019,46.338 87.759,46.338 88.497,45.6 88.497,44.039 R61.2@89.215,43.321 ; R61.2@89.144,43.251 R61.2@89.211,43.184
NetR68_2: R68.2 R69.1 U19.5 | length 2.3
  Top Layer w0.254: U19.5@97.573,43.529 R68.2@98.775,43.529 ; R68.2@98.822,43.575 98.822,42.463 R69.1@98.835,42.45
NetR74_1: R74.1 SB43.2 U5.98 | length 7.7
  Top Layer w0.2: v1(52.228,30.81) 52.228,31.351 51.906,31.673 51.906,32.095 51.913,32.102 51.913,32.867 52.313,33.267 U5.98@52.313,34.794
  Bottom Layer w0.2: 50.056,28.664 50.261,28.869 50.599,28.869 51.914,30.184 R74.1@52.165,30.184 52.301,30.32 52.228,30.392 v1(52.228,30.81)
NetR87_2: R87.2 X2.1 | length 1.3
  Bottom Layer w0.2: R87.2@21.555,49.511 21.603,49.463 X2.1@22.83,49.463
NetR91_2: R91.2 U24.2 | length 3.1
  Bottom Layer w0.2: U24.2@16.163,52.225 16.163,51.584 16.1,51.521 16.1,50.269 16.78,49.59 R91.2@16.78,49.453
NetR92_2: R92.2 U1.17 | length 3.6
  Top Layer w0.4: U1.17@29.15,24.999 29.178,25.026 v1(29.178,26.867)
  Bottom Layer w0.4: R92.2@28.442,28.194 28.603,28.194 29.178,27.619 v1(29.178,26.867)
